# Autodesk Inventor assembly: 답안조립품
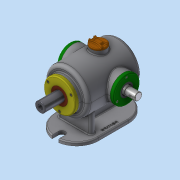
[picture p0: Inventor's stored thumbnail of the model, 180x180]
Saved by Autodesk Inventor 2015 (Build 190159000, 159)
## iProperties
Created: 2018-02
Part Number: 답안조립품
Document SubType Name: Assembly
Designer: SCD-A03
Mass: 7551.9 g
Surface Area: 3901.69 cm^2
Volume: 1791.93 cm^3
Density: 4.2144 g/cm^3
Author: SCD-A03
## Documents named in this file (16)
- C:\Users\SCD-A03\Desktop\380208V1004\답안조립품.iam
- C:\Users\SCD-A03\Desktop\380208V1004\본체.ipt
- C:\Users\SCD-A03\Desktop\380208V1004\가변스프링.ipt
- C:\Users\SCD-A03\Desktop\380208V1004\베어링 6205.ipt
- 베어링 6205.ipt
- C:\Users\SCD-A03\Desktop\380208V1004\본체커버.ipt
- C:\Users\SCD-A03\Desktop\380208V1004\볼트 M4.ipt
- C:\Users\SCD-A03\Desktop\380208V1004\부시.ipt
- C:\Users\SCD-A03\Desktop\380208V1004\상부 캡.ipt
- C:\Users\SCD-A03\Desktop\380208V1004\슬라이드 커버.ipt
- C:\Users\SCD-A03\Desktop\380208V1004\슬라이드.ipt
- C:\Users\SCD-A03\Desktop\380208V1004\오일실.ipt
- 오일실.ipt
- C:\Users\SCD-A03\Desktop\380208V1004\축 커버-1.ipt
- C:\Users\SCD-A03\Desktop\380208V1004\축 커버-2.ipt
- C:\Users\SCD-A03\Desktop\380208V1004\편심축.ipt
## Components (1 placed, 1 different names)
1. 가변스프링:1
